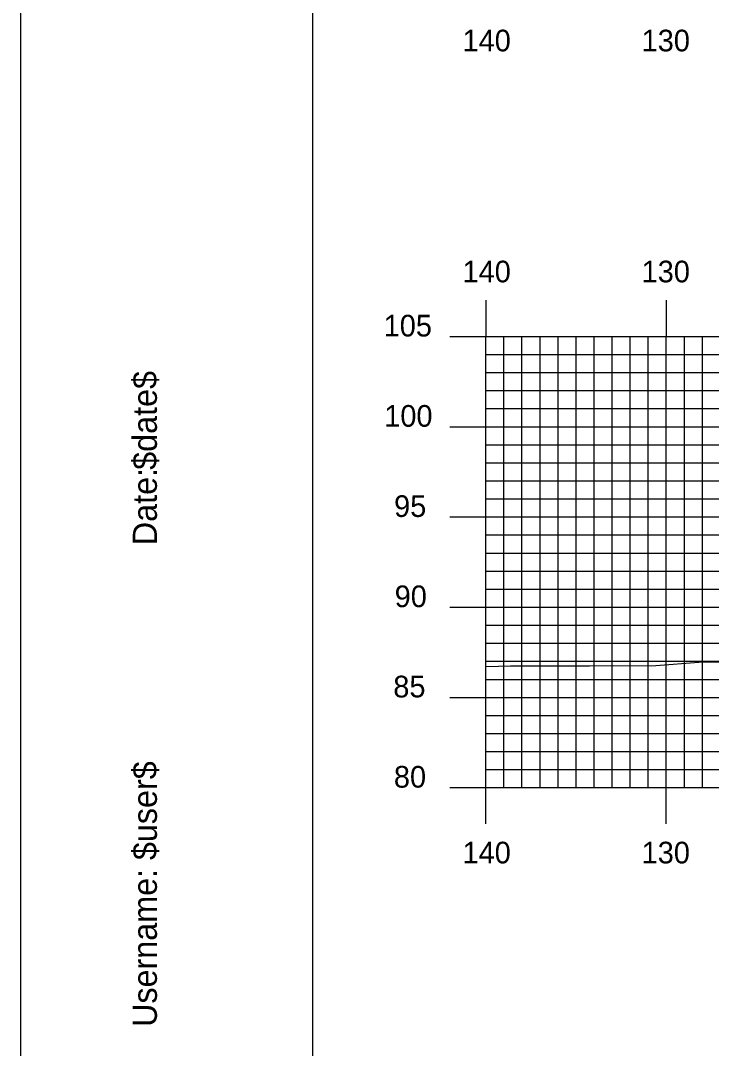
# Model space of a CAD drawing. Extents: x 1763365 to 1763708, y 442591 to 442811.
# Drawn here: x 1763365 to 1763403.3, y 442699.2 to 442756.2 of the extents above; entities that cross this region are included whole.
import ezdxf

# ---------------------------------------------------------------- set-up
doc = ezdxf.new("R2010")
doc.units = 0
for name, color, linetype in [('BORDER', 7, 'Continuous'), ('H_V ANNOTATION', 7, 'Continuous'), ('MAJOR', 7, 'Continuous'), ('MINOR', 7, 'Continuous'), ('PLOT BOUNDARY', 7, 'Continuous'), ('S_Roadway_Centerline', 7, 'Continuous')]:
    doc.layers.add(name, color=color, linetype=linetype)

msp = doc.modelspace()

# ---------------------------------------------------------------- linework, layer by layer
at = {"layer": 'BORDER'}
msp.add_lwpolyline([(1763381.205, 442596.665), (1763701.205, 442596.665), (1763701.205, 442806.665), (1763381.205, 442806.665)], close=True, dxfattribs=at)
at = {"layer": 'MAJOR'}
for p, q in [((1763390.805, 442740.669), (1763390.805, 442738.665)), ((1763400.805, 442740.669), (1763400.805, 442738.665)), ((1763388.801, 442738.665), (1763390.805, 442738.665)), ((1763390.805, 442738.665), (1763670.805, 442738.665)), ((1763390.805, 442713.665), (1763390.805, 442738.665)), ((1763390.805, 442713.665), (1763390.805, 442738.665)), ((1763390.805, 442738.665), (1763670.805, 442738.665)), ((1763400.805, 442713.665), (1763400.805, 442738.665)), ((1763388.801, 442733.665), (1763390.805, 442733.665)), ((1763390.805, 442733.665), (1763670.805, 442733.665)), ((1763388.801, 442728.665), (1763390.805, 442728.665)), ((1763390.805, 442728.665), (1763670.805, 442728.665)), ((1763388.801, 442723.665), (1763390.805, 442723.665)), ((1763390.805, 442723.665), (1763670.805, 442723.665)), ((1763388.801, 442718.665), (1763390.805, 442718.665)), ((1763390.805, 442718.665), (1763670.805, 442718.665)), ((1763388.801, 442713.665), (1763390.805, 442713.665)), ((1763390.805, 442713.665), (1763670.805, 442713.665)), ((1763390.805, 442713.665), (1763670.805, 442713.665)), ((1763390.805, 442711.661), (1763390.805, 442713.665)), ((1763400.805, 442711.661), (1763400.805, 442713.665))]:
    msp.add_line(p, q, dxfattribs=at)
at = {"layer": 'MINOR'}
for p, q in [((1763390.805, 442713.665), (1763390.805, 442738.665)), ((1763391.805, 442713.665), (1763391.805, 442738.665)), ((1763392.805, 442713.665), (1763392.805, 442738.665)), ((1763393.805, 442713.665), (1763393.805, 442738.665)), ((1763394.805, 442713.665), (1763394.805, 442738.665)), ((1763395.805, 442713.665), (1763395.805, 442738.665)), ((1763396.805, 442713.665), (1763396.805, 442738.665)), ((1763397.805, 442713.665), (1763397.805, 442738.665)), ((1763398.805, 442713.665), (1763398.805, 442738.665)), ((1763399.805, 442713.665), (1763399.805, 442738.665)), ((1763401.805, 442713.665), (1763401.805, 442738.665)), ((1763402.805, 442713.665), (1763402.805, 442738.665)), ((1763390.805, 442737.665), (1763670.805, 442737.665)), ((1763390.805, 442737.665), (1763392.809, 442737.665)), ((1763390.805, 442736.665), (1763670.805, 442736.665)), ((1763390.805, 442736.665), (1763392.809, 442736.665)), ((1763390.805, 442735.665), (1763670.805, 442735.665)), ((1763390.805, 442735.665), (1763392.809, 442735.665)), ((1763390.805, 442734.665), (1763670.805, 442734.665)), ((1763390.805, 442734.665), (1763392.809, 442734.665)), ((1763390.805, 442732.665), (1763670.805, 442732.665)), ((1763390.805, 442732.665), (1763392.809, 442732.665)), ((1763390.805, 442731.665), (1763670.805, 442731.665)), ((1763390.805, 442731.665), (1763392.809, 442731.665)), ((1763390.805, 442730.665), (1763670.805, 442730.665)), ((1763390.805, 442730.665), (1763392.809, 442730.665)), ((1763390.805, 442729.665), (1763670.805, 442729.665)), ((1763390.805, 442729.665), (1763392.809, 442729.665)), ((1763390.805, 442727.665), (1763670.805, 442727.665)), ((1763390.805, 442727.665), (1763392.809, 442727.665)), ((1763390.805, 442726.665), (1763670.805, 442726.665)), ((1763390.805, 442726.665), (1763392.809, 442726.665)), ((1763390.805, 442725.665), (1763670.805, 442725.665)), ((1763390.805, 442725.665), (1763392.809, 442725.665)), ((1763390.805, 442724.665), (1763670.805, 442724.665)), ((1763390.805, 442724.665), (1763392.809, 442724.665)), ((1763390.805, 442722.665), (1763670.805, 442722.665)), ((1763390.805, 442722.665), (1763392.809, 442722.665)), ((1763390.805, 442721.665), (1763670.805, 442721.665)), ((1763390.805, 442721.665), (1763392.809, 442721.665)), ((1763390.805, 442720.665), (1763670.805, 442720.665)), ((1763390.805, 442720.665), (1763392.809, 442720.665)), ((1763390.805, 442720.665), (1763670.805, 442720.665)), ((1763390.805, 442719.665), (1763670.805, 442719.665)), ((1763390.805, 442719.665), (1763392.809, 442719.665)), ((1763390.805, 442717.665), (1763670.805, 442717.665)), ((1763390.805, 442717.665), (1763392.809, 442717.665)), ((1763390.805, 442716.665), (1763670.805, 442716.665)), ((1763390.805, 442716.665), (1763392.809, 442716.665)), ((1763390.805, 442715.665), (1763670.805, 442715.665)), ((1763390.805, 442715.665), (1763392.809, 442715.665)), ((1763390.805, 442714.665), (1763670.805, 442714.665)), ((1763390.805, 442714.665), (1763392.809, 442714.665))]:
    msp.add_line(p, q, dxfattribs=at)
at = {"layer": 'PLOT BOUNDARY'}
msp.add_lwpolyline([(1763365.019, 442590.547), (1763705.019, 442590.547), (1763705.019, 442810.547), (1763365.019, 442810.547)], close=True, dxfattribs=at)
at = {"layer": 'S_Roadway_Centerline'}
msp.add_lwpolyline([(1763390.805, 442720.369), (1763391.498, 442720.404), (1763392.169, 442720.407), (1763392.874, 442720.41), (1763393.602, 442720.413), (1763394.344, 442720.416), (1763395.09, 442720.418), (1763395.828, 442720.42), (1763396.548, 442720.422), (1763397.889, 442720.424), (1763399.991, 442720.422), (1763402.846, 442720.628), (1763404.216, 442720.627)], dxfattribs=at)

# ---------------------------------------------------------------- texts
at = {"layer": 'BORDER'}
for s, p in [('$date$', (1763372.575, 442731.275)), ('Date:', (1763372.575, 442727.099)), ('$user$', (1763372.575, 442709.648)), ('Username:', (1763372.575, 442700.401))]:
    msp.add_text(s, height=1.3392, rotation=90, dxfattribs=at).set_placement(p)
at = {"layer": 'H_V ANNOTATION'}
for s, p in [('140', (1763389.51, 442754.465)), ('130', (1763399.435, 442754.465)), ('140', (1763389.51, 442741.665)), ('130', (1763399.435, 442741.665)), ('105', (1763385.14, 442738.665)), ('100', (1763385.172, 442733.665)), ('95', (1763385.718, 442728.665)), ('90', (1763385.75, 442723.665)), ('85', (1763385.675, 442718.665)), ('80', (1763385.707, 442713.665)), ('140', (1763389.51, 442709.465)), ('130', (1763399.435, 442709.465))]:
    msp.add_text(s, height=1.2, dxfattribs=at).set_placement(p)
at = {"layer": 'MAJOR'}
msp.add_text('-', height=0.012, dxfattribs=at).set_placement((1763390.797, 442713.665))

doc.saveas('drawing.dxf')
